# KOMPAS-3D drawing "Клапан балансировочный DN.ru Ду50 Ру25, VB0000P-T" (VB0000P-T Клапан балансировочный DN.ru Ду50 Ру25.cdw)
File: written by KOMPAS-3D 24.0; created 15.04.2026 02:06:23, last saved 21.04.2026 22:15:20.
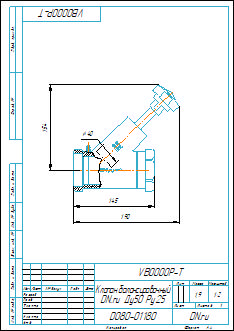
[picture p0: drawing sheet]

Document properties: Автор: DN.ru; Форматы листов документа: A4; Полное имя файла: VB0000P-T Клапан балансировочный DN.ru Ду50 Ру25.m3d; Масса: 1.9; Наименование: Клапан балансировочный DN.ru Ду50 Ру25; Количество листов документа: 1; Примечание: D080-01180

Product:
- Part/product: Клапан балансировочный DN.ru Ду50 Ру25  | designation VB0000P-T
    Масса: 1.9
    Раздел спецификации: Прочие изделия
    Примечание: D080-01180

Views: Вид 1, Местный разрез 1, Вид:1
Referenced files in C:\Работа\VB0000P-T DN X PN 25 Клапан балансировочный DN.ru\DN15\: VB0000P-T DN15 PN25 Клапан балансировочный DN.ru.m3d
Referenced files in E:\Работа\Зайцев\АУТСОРС\Диман\Балансировка\VB0000P-T Клапан балансировочный DN.ru Ду15-50 Ру25\DN50\: VB0000P-T Клапан балансировочный DN.ru Ду50 Ру25.m3d
Referenced files in C:\Program Files\ASCON\KOMPAS-3D v24\Templates\: Чертеж_DN.ru.cdt
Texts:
  VB0000P-T
  Чертеж_DN.ru.cdt
  Клапан балансировочный
  DN.ru Ду50 Ру25
  Клапан балансировочный DN.ru Ду50 Ру25
  VB0000P-T Клапан балансировочный DN.ru Ду50 Ру25
Dimensions and other numbers on the sheet: 0; 3; 2; 4; 145; 154; 190; 1:2; 1; 1,9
